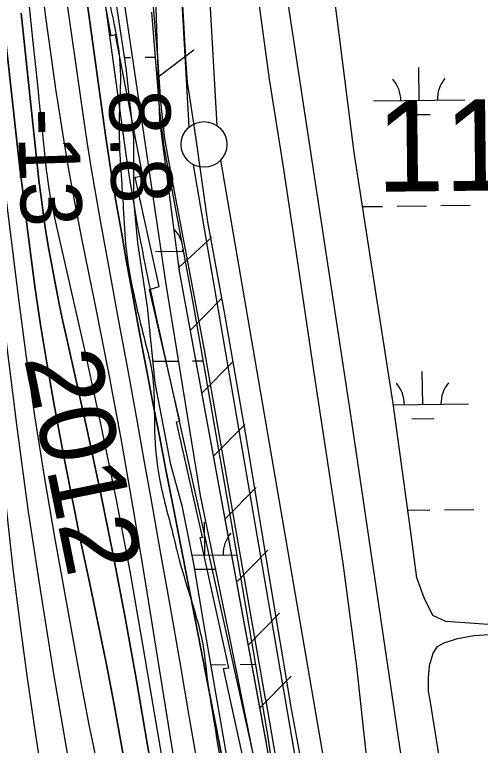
# Model space of a CAD drawing. Extents: x 3694830 to 3732949, y 415201 to 440970.
# Drawn here: x 3718720 to 3719230, y 422917 to 423717 of the extents above; entities that cross this region are included whole.
import ezdxf

# ---------------------------------------------------------------- set-up
doc = ezdxf.new("R2010")
doc.units = 0
for name, color, linetype in [('V-FLOD-BASE', 7, 'Continuous'), ('V-LEVE-TOET', 7, 'Continuous'), ('V-RIVR-EDGE', 7, 'Continuous'), ('V-RIVR-IDEN', 7, 'Continuous'), ('V-RIVR-RANG', 7, 'Continuous'), ('V-ROAD-CNTR', 7, 'Continuous'), ('V-RRAP-FSHR', 7, 'Continuous'), ('V-RRAP-RVMT', 7, 'Continuous'), ('V-SITE-VEGE', 7, 'Continuous'), ('V-SURV-IDEN', 7, 'Continuous'), ('V-SURV-LINE', 7, 'Continuous'), ('V-TOPO-DPTH', 7, 'Continuous'), ('V-TOPO-MAJR', 7, 'Continuous'), ('V-TOPO-MINR', 7, 'Continuous'), ('V-TOPO-WATR', 7, 'Continuous'), ('V-WETL-SWMP', 7, 'Continuous')]:
    doc.layers.add(name, color=color, linetype=linetype)

msp = doc.modelspace()

# ---------------------------------------------------------------- linework, layer by layer
at = {"layer": 'V-FLOD-BASE'}
msp.add_lwpolyline([(3719080.02, 422624.34), (3719063.04, 422730.6), (3719042.45, 422855.95), (3719023.92, 422954.99), (3718998.69, 423105.1), (3718976.05, 423242.31), (3718950.31, 423388.81), (3718931.77, 423489.91), (3718918.91, 423582.76), (3718912.73, 423621.45), (3718909.65, 423642.6), (3718908.11, 423662.72), (3718904.52, 423727.19), (3718897.86, 423854.08), (3718890.17, 423994.9), (3718881.45, 424124.37), (3718878.9, 424206.38), (3718876.85, 424256.42), (3718872.22, 424292.01), (3718861.41, 424355.97), (3718858.85, 424393.11), (3718851.68, 424539.09)], dxfattribs=at)
at = {"layer": 'V-LEVE-TOET'}
for points in [[(3719118.2, 422780.39), (3719107.6, 422885.67), (3719094.89, 423003.71), (3719080.04, 423116.43), (3719049.27, 423317.41), (3719031.24, 423440.76), (3719014.26, 423552.42), (3718999.41, 423646), (3718988.8, 423723.63), (3718977.14, 423810.83), (3718959.11, 423949.07), (3718952.77, 424062.85), (3718946.43, 424188.33), (3718936.91, 424323.37), (3718933.76, 424449.91), (3718931.68, 424566.88), (3718926.41, 424699.8), (3718917.93, 424783.81), (3718910.52, 424881.64), (3718900.98, 424966.71), (3718901, 425006.05), (3718898.88, 425044.34), (3718899.96, 425078.36)], [(3718995.09, 422968.13), (3718965.37, 423137.22), (3718928.23, 423349.9), (3718893.21, 423534.93), (3718884.71, 423580.66), (3718880.48, 423621.07), (3718877.3, 423669.98), (3718869.89, 423755.05), (3718865.68, 423879.47), (3718861.46, 423992.18), (3718856.19, 424108.09), (3718852.5, 424205.39), (3718851.45, 424235.69), (3718848.27, 424272.91), (3718841.37, 424310.66), (3718836.61, 424367.55), (3718826.56, 424506.85), (3718825.53, 424612.66)], [(3718995.09, 422968.13), (3719027.34, 422778.84), (3719054.17, 422625.88), (3719073.69, 422513.6), (3719080.19, 422480.79), (3719082.36, 422461.26), (3719084.25, 422442.28), (3719084.52, 422423.84), (3719085.34, 422398.34), (3719085.33, 422382.34), (3719086.15, 422373.67), (3719099.97, 422296.64), (3719112.98, 422232.64), (3719120.03, 422208.23), (3719131.69, 422169.72), (3719149.85, 422115.21)]]:
    msp.add_lwpolyline(points, dxfattribs=at)
at = {"layer": 'V-RIVR-EDGE'}
msp.add_spline([(3716285.15, 433216.71), (3716310.38, 433178.21), (3716330.2, 433149.68), (3716351.38, 433122.49), (3716380.66, 433076.75), (3716399.14, 433050.48), (3716447.79, 432976.21), (3716475.25, 432930.47), (3716501.83, 432891.07), (3716527.51, 432851.22), (3716586.04, 432749.34), (3716608.1, 432711.75), (3716608.09, 432707.68), (3716608.07, 432700.45), (3716613.02, 432690.94), (3716627.43, 432664.23), (3716633.27, 432651.55), (3716643.19, 432639.32), (3716675.17, 432589.5), (3716706.24, 432538.33), (3716726.94, 432498.04), (3716741.33, 432463.64), (3716748.51, 432442.82), (3716788.59, 432378.52), (3716817.43, 432339.56), (3716842.2, 432297.45), (3716889.46, 432209.61), (3716920.5, 432144.42), (3716938.04, 432109.56), (3716956.5, 432075.15), (3716988.92, 432022.62), (3717009.18, 431986.85), (3717026.3, 431960.13), (3717062.32, 431897.65), (3717093.37, 431840.15), (3717112.26, 431799.86), (3717149.12, 431711.14), (3717176.54, 431644.61), (3717201.25, 431580.79), (3717210.68, 431556.35), (3717248.47, 431478.94), (3717267.81, 431435.48), (3717289.41, 431392.93), (3717306.48, 431346.77), (3717328.07, 431301.04), (3717339.31, 431276.6), (3717352.34, 431244.01), (3717362.7, 431226.35), (3717376.21, 431205.52), (3717389.26, 431178.36), (3717401.37, 431141.7), (3717407.18, 431113.2), (3717409.87, 431101.89), (3717419.75, 431075.64), (3717452.49, 430968.85), (3717469.09, 430916.81), (3717483.44, 430865.23), (3717505.45, 430810.01), (3717526.57, 430753.44), (3717540.49, 430715.43), (3717579.07, 430593.25), (3717599.25, 430526.28), (3717616.31, 430474.69), (3717628.88, 430437.13), (3717638.74, 430405), (3717647.69, 430364.28), (3717653.48, 430331.72), (3717658.42, 430314.52), (3717667.85, 430290.08), (3717679.53, 430260.66), (3717690.34, 430242.1), (3717695.71, 430221.28), (3717698.37, 430200.03), (3717697.85, 430171.99), (3717701.42, 430152.99), (3717705.91, 430140.77), (3717716.26, 430119.95), (3717727.97, 430100.48), (3717735.6, 430076.49), (3717737.82, 430059.31), (3717749.05, 430029.89), (3717760.76, 430011.77), (3717771.56, 429990.04), (3717776.48, 429968.33), (3717783.19, 429941.63), (3717791.73, 429917.65), (3717803.43, 429898.63), (3717812.42, 429876.45), (3717819.16, 429857.44), (3717834.88, 429816.71), (3717846.52, 429770.11), (3717854.12, 429734.82), (3717863.55, 429706.31), (3717878.83, 429667.39), (3717891.37, 429622.59), (3717903.49, 429586.39), (3717917.82, 429530.29), (3717931.71, 429476.45), (3717959.46, 429363.79), (3717976.51, 429307.23), (3717987.25, 429262.44), (3718014.11, 429153.85), (3718027.51, 429090.07), (3718040.47, 429028.09), (3718052.52, 428962.5), (3718057.84, 428919.98), (3718056.9, 428903.25), (3718056.86, 428887.88), (3718057.71, 428868.43), (3718061.29, 428850.79), (3718065.77, 428833.6), (3718082.36, 428779.3), (3718091.33, 428748.08), (3718100.28, 428710.98), (3718111.45, 428657.14), (3718116.36, 428631.81), (3718128.31, 428525.97), (3718136.77, 428473.05), (3718141.66, 428440.03), (3718152.32, 428360.88), (3718163.9, 428291.22), (3718171.05, 428256.38), (3718178.23, 428236.47), (3718193.92, 428178.55), (3718199.74, 428157.29), (3718197.91, 428150.06), (3718196.52, 428133.33), (3718197.39, 428121.12), (3718204.12, 428098.04), (3718215.36, 428075.41), (3718227.96, 428049.6), (3718240.08, 428011.59), (3718242.71, 427978.58), (3718251.11, 427901.24), (3718254.15, 427852.85), (3718257.69, 427822.1), (3718271.5, 427736.15), (3718281.74, 427671.92), (3718287.91, 427606.34), (3718295.91, 427551.61), (3718303.87, 427477.44), (3718310.12, 427447.13), (3718323.14, 427407.76), (3718345.15, 427350.28), (3718351.41, 427321.78), (3718363.48, 427267.49), (3718378.28, 427217.26), (3718397.99, 427141.25), (3718402.87, 427105.52), (3718405.92, 427056.68), (3718404.86, 426993.38), (3718419.58, 426915.12), (3718427.13, 426857.67), (3718428.77, 426789.85), (3718439.53, 426753.19), (3718453.89, 426709.75), (3718458.33, 426677.18), (3718461.82, 426625.18), (3718465.34, 426583.57), (3718482.71, 426479.53), (3718492.52, 426423.89), (3718501, 426378.2), (3718502.74, 426350.16), (3718512.91, 426256.09), (3718518.23, 426213.12), (3718524.03, 426182.81), (3718533.44, 426148.88), (3718540.93, 426069.28), (3718548.93, 426010.93), (3718557.81, 425944.44), (3718573.42, 425858.94), (3718584.55, 425787.48), (3718587.61, 425745.42), (3718587.56, 425725.97), (3718607.51, 425567.22), (3718614.55, 425488.07), (3718638.22, 425368.64), (3718641.26, 425318.45), (3718641.09, 425249.72), (3718640.1, 425214), (3718649.84, 425130.78), (3718658.73, 425069.26), (3718661.82, 425037.15), (3718660.41, 425016.36), (3718674.96, 424864.4), (3718675.73, 424812.85), (3718692.62, 424694.79), (3718696.05, 424618.82), (3718696.4, 424575.87), (3718706.12, 424484.51), (3718711.87, 424431.59), (3718715.41, 424403.09), (3718735.93, 424289.1), (3718746.6, 424215.37), (3718759.9, 424108.63), (3718772.36, 424027.21), (3718777.72, 423998.26), (3718795.91, 423858.04), (3718805.72, 423804.21), (3718812.44, 423776.61), (3718829, 423707.39), (3718835.67, 423662.61), (3718835.09, 423611.97), (3718835, 423576.7), (3718839.35, 423505.25), (3718842.4, 423460.03), (3718850.42, 423412.53), (3718863.4, 423357.79), (3718870.56, 423326.57), (3718873.56, 423260.55), (3718878.86, 423208.99), (3718893.63, 423148.36), (3718899, 423126.2), (3718912.45, 423080.04), (3718927.23, 423022.58), (3718930.77, 422992.73), (3718937.45, 422950.21), (3718945.92, 422900.45), (3718952.63, 422870.59), (3718968.72, 422795.95), (3718969.56, 422769.72), (3718968.13, 422738.52), (3718972.12, 422707.77), (3718981.05, 422661.17), (3718990.85, 422602.82), (3719006.89, 422506.47), (3719010.81, 422446.32), (3719014.37, 422425.06), (3719022.44, 422393.39), (3719033.2, 422359), (3719050.26, 422307.87), (3719062.77, 422249.05), (3719077.1, 422190.24), (3719087.85, 422149.06)], degree=3, dxfattribs=at)
at = {"layer": 'V-ROAD-CNTR'}
msp.add_lwpolyline([(3718947.54, 424793.91), (3718963.96, 424411.35), (3718982.23, 424062.26), (3719015.21, 423758.25), (3719087.26, 423283.48), (3719154.04, 422831.8), (3719191.49, 422587.83), (3719255.86, 422328.26), (3719350.65, 422063.91), (3719444.22, 421874.4), (3719568.78, 421676.55), (3719728.14, 421465.73), (3719881.17, 421306.92), (3720024.62, 421178.58), (3720151.91, 421084.41), (3720292.89, 420993.44), (3720460.72, 420905.92), (3720538.94, 420876.02)], dxfattribs=at)
at = {"layer": 'V-RRAP-FSHR'}
for p, q in [((3718877.5, 423648.66), (3718916.57, 423677.95)), ((3718900.11, 423440.07), (3718936.13, 423473.04)), ((3718912.58, 423371.2), (3718946.85, 423405.99)), ((3718925.26, 423302.36), (3718959.53, 423337.15)), ((3718937.95, 423233.53), (3718972.21, 423268.32)), ((3718950.62, 423164.69), (3718984.89, 423199.48)), ((3718963.31, 423095.85), (3718997.57, 423130.64)), ((3718975.99, 423027.01), (3719010.25, 423061.8)), ((3718988.67, 422958.17), (3719022.93, 422992.96))]:
    msp.add_line(p, q, dxfattribs=at)
for points in [[(3718391.12, 427348.28), (3718475.54, 426733.12), (3718537.58, 426315.32), (3718574.68, 426010.61), (3718621.14, 425693.56), (3718655.82, 425402.36), (3718689.05, 424990.86), (3718733.51, 424580.69), (3718746.96, 424380.12), (3718784.4, 424103.55), (3718845.23, 423695.11), (3718886.06, 423421.61), (3718923.4, 423190.48), (3718957.44, 423026.17), (3718988.34, 422871.6), (3719013.63, 422718.01), (3719111.7, 422210.46), (3719157.05, 422005.7), (3719219.83, 421828.02), (3719374.72, 421477.77), (3719529.57, 421100.78)], [(3718800.84, 424873.2), (3718834.34, 424280.67), (3718875.05, 423724.21), (3718879.05, 423600.67), (3718900.65, 423436), (3718998.44, 422905.14), (3719048.2, 422575.21), (3719088.23, 422325.46), (3719124.79, 422190.56), (3719166.99, 422050.62), (3719263.65, 421833.39), (3719401.62, 421600.06), (3719571.68, 421363.46), (3719742.72, 421175.31), (3719823.11, 421106.31)], [(3718830.68, 424345.43), (3718834.34, 424280.67), (3718875.05, 423724.21), (3718878, 423633.21)], [(3718899.62, 423443.84), (3718900.65, 423436), (3718995.73, 422919.8)]]:
    msp.add_lwpolyline(points, dxfattribs=at)
at = {"layer": 'V-RRAP-RVMT'}
for p, q in [((3718825.88, 423693.38), (3718803.78, 423816.48)), ((3718830.78, 423694.42), (3718825.88, 423693.38)), ((3718860.77, 423540.36), (3718830.78, 423694.42)), ((3718852.24, 423538.82), (3718860.77, 423540.36)), ((3718878.45, 423419.09), (3718852.24, 423538.82)), ((3718867.89, 423416.05), (3718878.45, 423419.09)), ((3718901.06, 423271.78), (3718867.89, 423416.05)), ((3718897.7, 423271.04), (3718901.06, 423271.78)), ((3718926.09, 423145.1), (3718897.7, 423271.04)), ((3718923.45, 423144.68), (3718926.09, 423145.1)), ((3718954.92, 423002.16), (3718923.45, 423144.68)), ((3718948.84, 423001.18), (3718954.92, 423002.16)), ((3718979.53, 422863.1), (3718948.84, 423001.18))]:
    msp.add_line(p, q, dxfattribs=at)
at = {"layer": 'V-SITE-VEGE'}
for p, q in [((3719205.08, 423034.34), (3719223.27, 423037.5)), ((3719223.27, 423037.5), (3719240.27, 423038.68)), ((3719183.34, 423025.26), (3719190.46, 423029.6)), ((3719190.46, 423029.6), (3719205.08, 423034.34)), ((3719178.59, 423018.15), (3719183.34, 423025.26)), ((3719174.63, 423004.7), (3719178.59, 423018.15)), ((3719173.44, 422991.27), (3719174.63, 423004.7)), ((3719173.44, 422976.64), (3719173.44, 422991.27)), ((3719175.8, 422964.38), (3719173.44, 422976.64)), ((3719187.64, 422890.05), (3719175.8, 422964.38))]:
    msp.add_line(p, q, dxfattribs=at)
at = {"layer": 'V-SURV-LINE'}
for points in [[(3718911.6, 423593.74), (3718830.65, 425022.23)], [(3718860.6, 425023.9), (3718941.55, 423595.42)], [(3718945.87, 423557.48), (3719130.67, 422482.16)], [(3719101.1, 422477.08), (3718916.3, 423552.4)]]:
    msp.add_lwpolyline(points, dxfattribs=at)
msp.add_circle((3718927.71, 423574.63), 25, dxfattribs=at)
at = {"layer": 'V-TOPO-DPTH'}
for points in [[(3719042.78, 422082.04), (3718907.38, 422824.27), (3718862.2, 423105.39), (3718849.86, 423179.27), (3718836.92, 423253.05), (3718823.07, 423326.67), (3718808.63, 423400.17), (3718794.82, 423468.25), (3718787.13, 423507.69), (3718779.83, 423547.19), (3718773.13, 423586.81), (3718766.83, 423626.49), (3718766.24, 423630.39), (3718760.2, 423672.12), (3718754.53, 423713.88), (3718749.4, 423755.72), (3718744.62, 423797.61), (3718680.78, 424391.78), (3718678.26, 424414.82), (3718675.68, 424437.85), (3718673.02, 424460.86), (3718670.31, 424483.88), (3718583.05, 425211.38)], [(3719042.78, 422082.04), (3718907.38, 422824.27), (3718862.2, 423105.39), (3718849.86, 423179.27), (3718836.92, 423253.05), (3718823.07, 423326.67), (3718808.63, 423400.17), (3718794.82, 423468.25), (3718787.13, 423507.69), (3718779.83, 423547.19), (3718773.13, 423586.81), (3718766.83, 423626.49), (3718766.24, 423630.39), (3718760.2, 423672.12), (3718754.53, 423713.88), (3718749.4, 423755.72), (3718744.62, 423797.61), (3718680.78, 424391.78), (3718678.26, 424414.82), (3718675.68, 424437.85), (3718673.02, 424460.86), (3718670.31, 424483.88), (3718583.05, 425211.38)], [(3718631.74, 424398.42), (3718722.75, 423578.16), (3718724.6, 423561.83), (3718726.49, 423545.51), (3718728.46, 423529.2), (3718730.47, 423512.89), (3718736.94, 423461.34), (3718742.58, 423419.31), (3718748.72, 423377.36), (3718755.58, 423335.53), (3718762.93, 423293.77), (3718766.99, 423271.81), (3718775.35, 423227.69), (3718783.98, 423183.62), (3718792.99, 423139.62), (3718802.27, 423095.68), (3718811.5, 423051.73), (3718820.42, 423007.72), (3718828.86, 422963.62), (3718836.98, 422919.45), (3718846.47, 422866.25)], [(3718631.74, 424398.42), (3718722.75, 423578.16), (3718724.6, 423561.83), (3718726.49, 423545.51), (3718728.46, 423529.2), (3718730.47, 423512.89), (3718736.94, 423461.34), (3718742.58, 423419.31), (3718748.72, 423377.36), (3718755.58, 423335.53), (3718762.93, 423293.77), (3718766.99, 423271.81), (3718775.35, 423227.69), (3718783.98, 423183.62), (3718792.99, 423139.62), (3718802.27, 423095.68), (3718811.5, 423051.73), (3718820.42, 423007.72), (3718828.86, 422963.62), (3718836.98, 422919.45), (3718846.47, 422866.25)], [(3718809.12, 422905.12), (3718805.58, 422922.43), (3718802.04, 422939.74), (3718798.6, 422957.07), (3718795.3, 422974.43), (3718792.1, 422991.81), (3718764.49, 423145.05), (3718753.1, 423211.42), (3718742.45, 423277.89), (3718732.91, 423344.53), (3718724.1, 423411.28), (3718713.93, 423493.7), (3718710.81, 423519.33), (3718707.77, 423544.97), (3718704.82, 423570.62), (3718701.94, 423596.29), (3718652.54, 424044.65)], [(3718809.12, 422905.12), (3718805.58, 422922.43), (3718802.04, 422939.74), (3718798.6, 422957.07), (3718795.3, 422974.43), (3718792.1, 422991.81), (3718764.49, 423145.05), (3718753.1, 423211.42), (3718742.45, 423277.89), (3718732.91, 423344.53), (3718724.1, 423411.28), (3718713.93, 423493.7), (3718710.81, 423519.33), (3718707.77, 423544.97), (3718704.82, 423570.62), (3718701.94, 423596.29), (3718652.54, 424044.65)], [(3718756.67, 424041.42), (3718820.37, 423582.17), (3718822.8, 423565.28), (3718825.36, 423548.41), (3718828.08, 423531.56), (3718830.93, 423514.73), (3718837.2, 423478.74), (3718843.36, 423443.95), (3718849.63, 423409.18), (3718856.06, 423374.44), (3718862.61, 423339.72), (3718864.03, 423332.25), (3718871.4, 423293.82), (3718878.81, 423255.39), (3718886.26, 423216.97), (3718893.74, 423178.56), (3718951.57, 422882.83)], [(3718727.37, 423718.1), (3718744.25, 423559.52), (3718744.99, 423552.79), (3718745.75, 423546.06), (3718746.55, 423539.34), (3718747.37, 423532.62), (3718750.04, 423511.4), (3718752.38, 423494.1), (3718754.93, 423476.83), (3718757.81, 423459.62), (3718760.9, 423442.44), (3718761.67, 423438.41), (3718765.4, 423419.26), (3718769.25, 423400.14), (3718773.28, 423381.05), (3718777.43, 423361.99), (3718799.28, 423264), (3718813.96, 423195.87), (3718827.96, 423127.6), (3718840.98, 423059.13), (3718853.32, 422990.54), (3718869.63, 422895.94)], [(3718869.63, 422895.94), (3718853.32, 422990.54), (3718840.98, 423059.13), (3718827.96, 423127.6), (3718813.96, 423195.87), (3718799.28, 423264), (3718777.43, 423361.99), (3718773.28, 423381.05), (3718769.25, 423400.14), (3718765.4, 423419.26), (3718761.67, 423438.41), (3718760.9, 423442.44), (3718757.81, 423459.62), (3718754.93, 423476.83), (3718752.38, 423494.1), (3718750.04, 423511.4), (3718747.37, 423532.62), (3718746.55, 423539.34), (3718745.75, 423546.06), (3718744.99, 423552.79), (3718744.25, 423559.52), (3718727.37, 423718.1)]]:
    msp.add_lwpolyline(points, dxfattribs=at)
at = {"layer": 'V-TOPO-MAJR'}
msp.add_lwpolyline([(3718932.64, 422074.53), (3718824.42, 422656.59), (3718819.48, 422682.96), (3718814.51, 422709.32), (3718809.48, 422735.67), (3718804.4, 422762.01), (3718796.78, 422801.34), (3718795.51, 422808.02), (3718794.27, 422814.7), (3718793.08, 422821.39), (3718791.91, 422828.08), (3718763.76, 422993.49), (3718749.23, 423082.99), (3718735.62, 423172.62), (3718723.38, 423262.45), (3718712.07, 423352.42), (3718697.6, 423475.08), (3718693.56, 423509.76), (3718689.58, 423544.44), (3718685.69, 423579.14), (3718681.87, 423613.84), (3718667.68, 423744.12)], dxfattribs=at)
at = {"layer": 'V-TOPO-MINR'}
for points in [[(3719042.78, 422082.04), (3718907.38, 422824.27), (3718862.2, 423105.39), (3718849.86, 423179.27), (3718836.92, 423253.05), (3718823.07, 423326.67), (3718808.63, 423400.17), (3718794.82, 423468.25), (3718787.13, 423507.69), (3718779.83, 423547.19), (3718773.13, 423586.81), (3718766.83, 423626.49), (3718766.24, 423630.39), (3718760.2, 423672.12), (3718754.53, 423713.88), (3718749.4, 423755.72), (3718744.62, 423797.61), (3718680.78, 424391.78), (3718678.26, 424414.82), (3718675.68, 424437.85), (3718673.02, 424460.86), (3718670.31, 424483.88), (3718583.05, 425211.38)], [(3718884.99, 422884.4), (3718860.85, 423027.66), (3718846.67, 423107.67), (3718831.61, 423187.51), (3718815.2, 423267.09), (3718797.9, 423346.49), (3718764.39, 423494.35), (3718763.21, 423499.7), (3718762.06, 423505.05), (3718760.97, 423510.41), (3718759.91, 423515.79), (3718759.72, 423516.74), (3718758.83, 423521.65), (3718758, 423526.57), (3718757.27, 423531.5), (3718756.6, 423536.44), (3718755.83, 423542.5), (3718755.6, 423544.42), (3718755.37, 423546.34), (3718755.16, 423548.26), (3718754.95, 423550.19), (3718750.47, 423593.06), (3718748.04, 423616.42), (3718745.6, 423639.79), (3718743.17, 423663.15), (3718740.75, 423686.51), (3718666.3, 424403.7)], [(3718846.47, 422866.25), (3718836.98, 422919.45), (3718828.86, 422963.62), (3718820.42, 423007.72), (3718811.5, 423051.73), (3718802.27, 423095.68), (3718792.99, 423139.62), (3718783.98, 423183.62), (3718775.35, 423227.69), (3718766.99, 423271.81), (3718762.93, 423293.77), (3718755.58, 423335.53), (3718748.72, 423377.36), (3718742.58, 423419.31), (3718736.94, 423461.34), (3718730.47, 423512.89), (3718728.46, 423529.2), (3718726.49, 423545.51), (3718724.6, 423561.83), (3718722.75, 423578.16), (3718631.74, 424398.42)], [(3718991.37, 422863.99), (3718874.74, 423390.32), (3718871.23, 423406.4), (3718867.79, 423422.5), (3718864.47, 423438.62), (3718861.21, 423454.75), (3718860.91, 423456.26), (3718857.93, 423471.66), (3718855.04, 423487.08), (3718852.28, 423502.52), (3718849.61, 423517.98), (3718846.86, 423534.35), (3718845.67, 423541.64), (3718844.52, 423548.94), (3718843.44, 423556.25), (3718842.4, 423563.56), (3718736.76, 424332.3)], [(3718809.12, 422905.12), (3718805.58, 422922.43), (3718802.04, 422939.74), (3718798.6, 422957.07), (3718795.3, 422974.43), (3718792.1, 422991.81), (3718764.49, 423145.05), (3718753.1, 423211.42), (3718742.45, 423277.89), (3718732.91, 423344.53), (3718724.1, 423411.28), (3718713.93, 423493.7), (3718710.81, 423519.33), (3718707.77, 423544.97), (3718704.82, 423570.62), (3718701.94, 423596.29), (3718652.54, 424044.65)], [(3719055.26, 422073.19), (3718936.82, 422801.31), (3718934.76, 422813.87), (3718932.68, 422826.42), (3718930.56, 422838.96), (3718928.42, 422851.5), (3718911.93, 422947.53), (3718901.46, 423008.07), (3718890.9, 423068.59), (3718880.18, 423129.09), (3718869.38, 423189.57), (3718863.38, 423222.88), (3718853.6, 423277.05), (3718843.76, 423331.21), (3718833.86, 423385.35), (3718823.91, 423439.49), (3718813.96, 423493.39), (3718809.11, 423520.6), (3718804.49, 423547.84), (3718800.21, 423575.14), (3718796.15, 423602.47), (3718774.69, 423753.32)], [(3718903.03, 422094.94), (3718867.24, 422273.09), (3718849.3, 422362.84), (3718831.5, 422452.62), (3718813.88, 422542.44), (3718796.39, 422632.28), (3718770.39, 422766.55), (3718766.13, 422789.3), (3718762.03, 422812.08), (3718758.2, 422834.91), (3718754.55, 422857.77), (3718743.24, 422931.22), (3718734.48, 422990.89), (3718726.27, 423050.63), (3718718.89, 423110.47), (3718712.06, 423170.39), (3718681.39, 423457.29), (3718676.77, 423500.61), (3718672.14, 423543.92), (3718667.51, 423587.24), (3718662.89, 423630.55), (3718662.77, 423631.62), (3718658.04, 423675.47), (3718653.24, 423719.31)], [(3718869.63, 422895.94), (3718853.32, 422990.54), (3718840.98, 423059.13), (3718827.96, 423127.6), (3718813.96, 423195.87), (3718799.28, 423264), (3718777.43, 423361.99), (3718773.28, 423381.05), (3718769.25, 423400.14), (3718765.4, 423419.26), (3718761.67, 423438.41), (3718760.9, 423442.44), (3718757.81, 423459.62), (3718754.93, 423476.83), (3718752.38, 423494.1), (3718750.04, 423511.4), (3718747.37, 423532.62), (3718746.55, 423539.34), (3718745.75, 423546.06), (3718744.99, 423552.79), (3718744.25, 423559.52), (3718727.37, 423718.1)]]:
    msp.add_lwpolyline(points, dxfattribs=at)
at = {"layer": 'V-TOPO-WATR'}
msp.add_lwpolyline([(3718951.57, 422882.83), (3718893.74, 423178.56), (3718886.26, 423216.97), (3718878.81, 423255.39), (3718871.4, 423293.82), (3718864.03, 423332.25), (3718862.61, 423339.72), (3718856.06, 423374.44), (3718849.63, 423409.18), (3718843.36, 423443.95), (3718837.2, 423478.74), (3718830.93, 423514.73), (3718828.08, 423531.56), (3718825.36, 423548.41), (3718822.8, 423565.28), (3718820.37, 423582.17), (3718756.67, 424041.42)], dxfattribs=at)
at = {"layer": 'V-WETL-SWMP'}
for p, q in [((3719075.49, 423695.4), (3719068, 423755.5)), ((3719092.05, 423565.72), (3719075.49, 423695.4)), ((3718840.81, 423669.71), (3718847.3, 423669.79)), ((3718863.29, 423669.98), (3718874.15, 423670.11)), ((3719163.15, 423622.81), (3719162.72, 423658.81)), ((3719113.15, 423622.21), (3719213.15, 423623.41)), ((3719151.33, 423607.24), (3719175.33, 423607.52)), ((3719116.51, 423408.36), (3719092.05, 423565.72)), ((3719139.12, 423507.08), (3719171.12, 423507.46)), ((3719187.12, 423507.65), (3719219.11, 423508.04)), ((3719101.23, 423506.63), (3719123.12, 423506.89)), ((3718874.67, 423457.5), (3718905.01, 423457.86)), ((3719134.65, 423291.34), (3719116.51, 423408.36)), ((3718871.92, 423337.38), (3718899.26, 423337.71)), ((3718915.26, 423337.9), (3718926.62, 423338.04)), ((3719167.12, 423290.16), (3719166.69, 423326.16)), ((3719153.97, 423150.59), (3719134.65, 423291.34)), ((3719134.87, 423289.77), (3719217.11, 423290.75)), ((3719155.3, 423274.58), (3719179.3, 423274.87)), ((3719150.69, 423174.52), (3719175.08, 423174.81)), ((3719191.08, 423175), (3719223.08, 423175.38)), ((3718928.64, 423125.44), (3718928.21, 423161.44)), ((3719160.68, 423100.37), (3719153.97, 423150.59)), ((3718914.53, 423125.27), (3718963.4, 423125.86)), ((3718917.46, 423109.88), (3718940.82, 423110.15)), ((3719168.58, 423078.63), (3719160.68, 423100.37)), ((3719178.06, 423059.25), (3719168.58, 423078.63)), ((3719192.29, 423052.92), (3719178.06, 423059.25)), ((3719252.38, 423048.55), (3719192.29, 423052.92)), ((3718935.16, 423005.44), (3718951.22, 423005.63)), ((3718967.22, 423005.82), (3718983.92, 423006.02))]:
    msp.add_line(p, q, dxfattribs=at)
for points in [[(3718952.86, 422903.43), (3718927.39, 423050.18), (3718916.78, 423113.98), (3718904.04, 423177.79), (3718891.3, 423224.58), (3718884.93, 423258.61), (3718874.32, 423313.91), (3718865.84, 423396.85), (3718855.23, 423467.04), (3718850.99, 423513.83), (3718851.02, 423581.88), (3718842.54, 423658.44), (3718825.56, 423769.04)], [(3718870.21, 423719.28), (3718878.87, 423611.35), (3718883.6, 423572.21), (3718915.95, 423399.43), (3718957.38, 423161.03), (3718996.44, 422932.9), (3719025.63, 422742.73)]]:
    msp.add_lwpolyline(points, dxfattribs=at)
for centre, start, end in [((3719107.9, 423622.62), 359.91153, 41.45519), ((3719218.38, 423623.94), 139.91153, 181.45518), ((3718869.42, 423457.91), 17.78281, 41.45519), ((3718869.42, 423457.91), 359.91153, 3.43344), ((3719111.87, 423289.97), 359.91153, 41.45519), ((3719222.35, 423291.29), 139.91153, 181.45518), ((3718983.87, 423126.57), 139.91153, 181.45519)]:
    msp.add_arc(centre, 35.25, start, end, dxfattribs=at)

# ---------------------------------------------------------------- texts
at = {"layer": 'V-RIVR-IDEN'}
msp.add_text(' 2012', height=83, rotation=281.5456, dxfattribs=at).set_placement((3718724.21, 423371.33))
at = {"layer": 'V-RIVR-RANG'}
for s, rotation, p in [('8.8', 271.51833, (3718823.43, 423633.9)), ('-13', 271.80306, (3718723.61, 423613.15))]:
    msp.add_text(s, height=67, rotation=rotation, dxfattribs=at).set_placement(p)
at = {"layer": 'V-SURV-IDEN'}
msp.add_text('1101+33.9', height=100, rotation=0.63052, dxfattribs=at).set_placement((3719116.66, 423522.78))

doc.saveas('drawing.dxf')
